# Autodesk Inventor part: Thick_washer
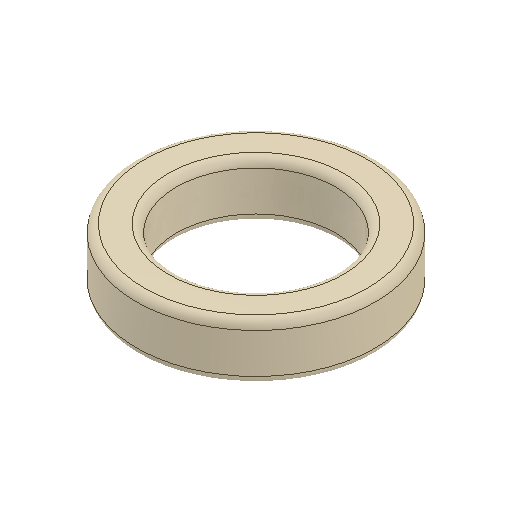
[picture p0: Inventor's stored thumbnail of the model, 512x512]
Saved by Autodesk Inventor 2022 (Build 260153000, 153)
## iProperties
Created: 2020-10
Part Number: Thick_washer
Material: Generico
Document SubType Name: Modeling
Designer: admin
Density: 1 g/cm^3
Appearance: Default
Author: admin
Sending System: SolidWorks 2020
Last Author: Simon
Last Saved: 2020-10-30
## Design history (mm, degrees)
fillet "Fillet1"
node "Solido1"
